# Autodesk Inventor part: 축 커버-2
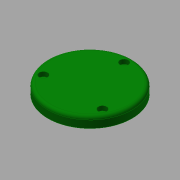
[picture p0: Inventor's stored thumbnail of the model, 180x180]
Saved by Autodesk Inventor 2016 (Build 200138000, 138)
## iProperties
Created: 2015-10
Part Number: 축 커버-2
Document SubType Name: Modeling
Designer: mdu
Density: 7.86 g/cm^3
Material: 강철, 연강
Appearance: 진녹색
Mass: 405.676 g
Surface Area: 133.169 cm^2
Volume: 51.6127 cm^3
Author: mdu
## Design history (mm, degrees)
sketch "스케치1"
  geometry: C1 r 40 at (0, 0) reference; C2 r 26 at (0, 0) reference; 1 further point
  node "참조1"
  node "참조2"
extrude "돌출1" new body sketch "스케치1" distance "d0" = 10; taper "d1" = 0 deg
extrude "돌출2" join sketch "스케치1" distance "d2" = 3; taper "d3" = 0 deg
sketch "스케치2"
  geometry: C1 r 20 at (0, 0); 1 further point
  constraints: 1 centre point, 1 coincident
  dimensions: "d13" = 40 diameter of C1
extrude "돌출3" cut sketch "스케치2" distance "d14" = 3; taper "d15" = 0 deg
sketch "스케치3"
  geometry: C1 r 1.621 at (0, 32.5) reference; 1 further point
hole "구멍2" sketch "스케치3" at (0, 32.5) diameter "d16" = 4.5; stored, may be unused: countersink angle "d20" = 90 deg, drill point angle "d22" = 118 deg; dims "d17" = 6, "d18" = 8, "d19" = 4.4, "d21" = 8
fillet "모깎기1" dims "d26" = 3, "d27" = 0.3
chamfer "모따기1" distance "d28" = 1; stored, may be unused: second distance "d29" = 2, angle "d30" = 45 deg
node "솔리드1"
pattern_circular "원형 패턴1" dims angle "d24" = 360 deg
node "참조3"
